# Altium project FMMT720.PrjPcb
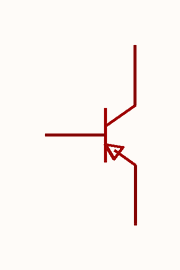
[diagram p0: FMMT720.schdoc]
1 sheet, 1 parts. Net scope: global (net labels, ports and power ports of the same name join across sheets).

## Sheet FMMT720.schdoc
size 127 x 101 mm

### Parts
Q?  fmmt720_c83675  [SOT-23-3_L2.9-W1.6-P1.90-LS2.8-BR]  (value not drawn)

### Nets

Not connected (* = marked no-connect by the designer): Q? 1(B) 2(E) 3(C)

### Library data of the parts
Q? = fmmt720_c83675: 晶体管类型:PNP;集电极电流(Ic):1.5A;集射极击穿电压(Vceo):40V;耗散功率(Pd):350mW;直流电流增益(hFE):300;; Manufacturer: CJ(江苏长电/长晶); AddInBom: yes; ModelId: 89cb27a44ab2466697082bb9fd73a7d0; ModelName: SOT-23-3L_L2.9-W1.6-H1.1-LS2.8-P0.95; ModelTransform: 114.173,110.236,0,90,0,0,0,0,0; type: PNP; Current - Collector(Ic): 1.5A; Collector - Emitter Voltage VCEO: 40V; Pd - Power Dissipation: 350mW; DC Current Gain: 300; Transition frequency(fT): 150MHz; Current - Collector Cutoff: 100nA; Vce Saturation(VCE(sat)): 330mV; Emitter-Base Voltage(Vebo): 5V; Number: 1个PNP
